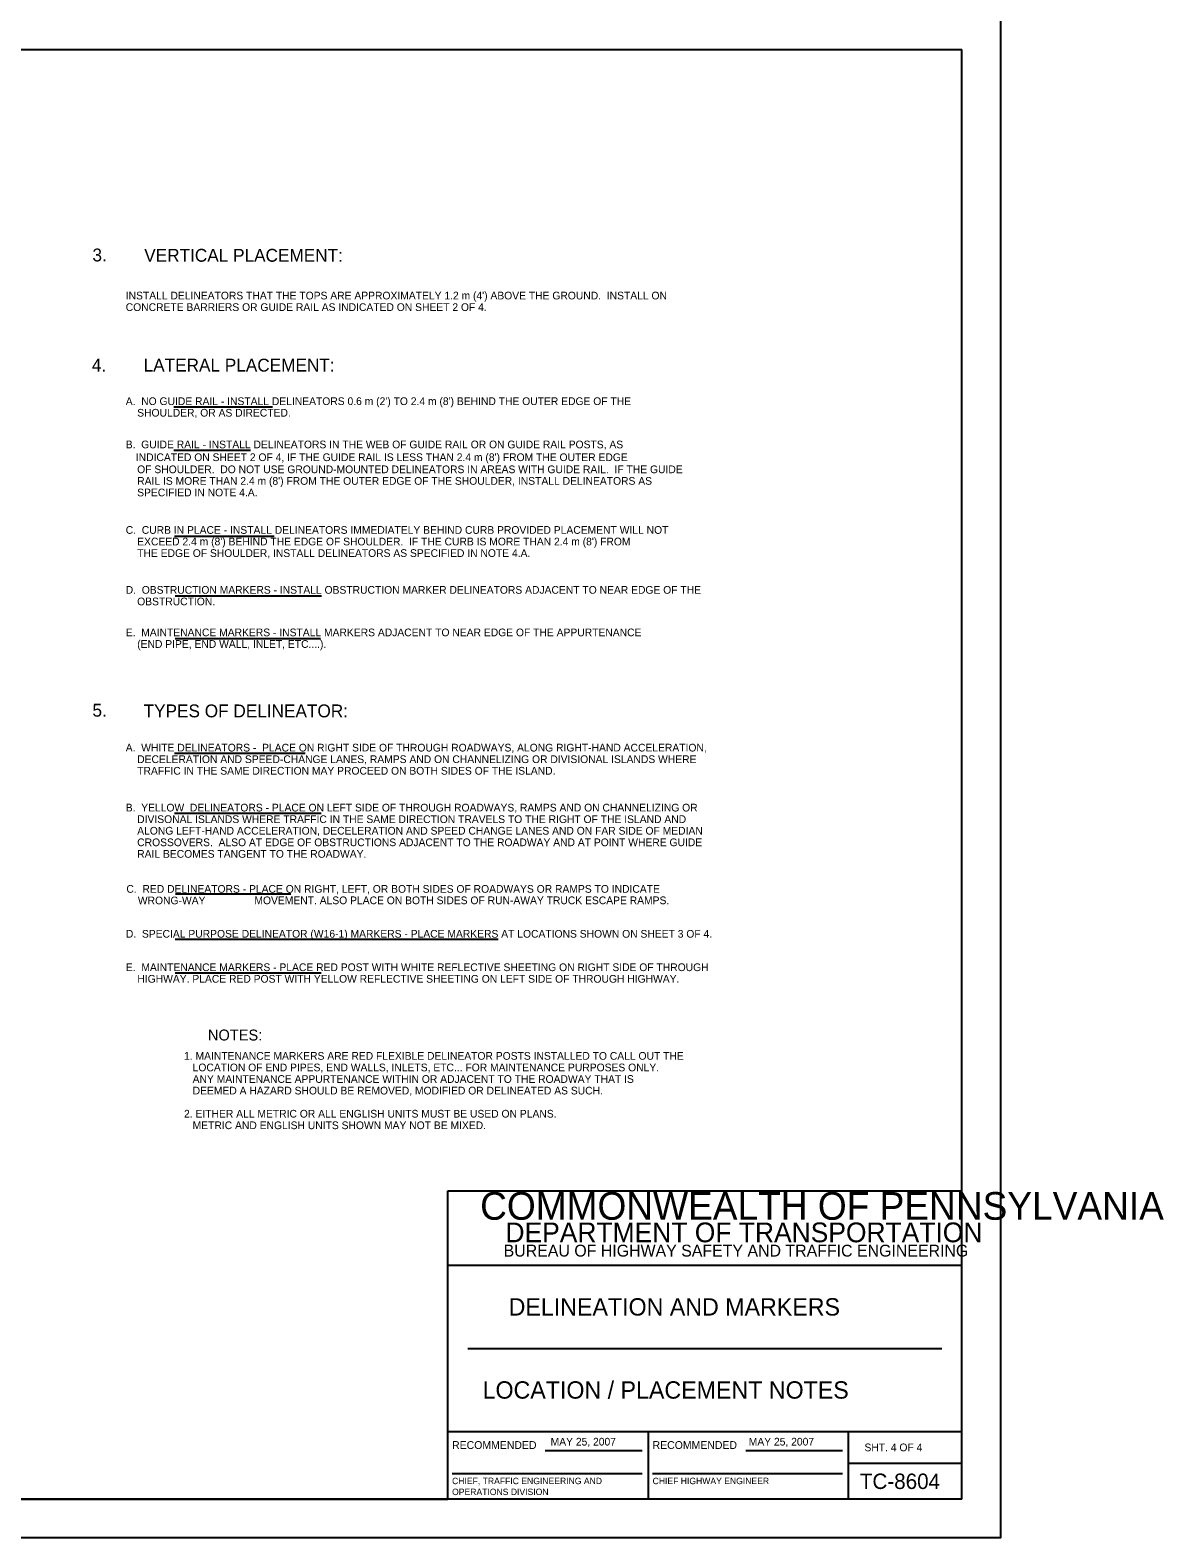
# Model space of a CAD drawing. Extents: x 640253 to 641999, y 298458 to 299646.
# Drawn here: x 641558 to 641999, y 298458 to 299044 of the extents above; entities that cross this region are included whole.
import ezdxf

# ---------------------------------------------------------------- set-up
doc = ezdxf.new("R2010")
doc.units = 0
for name, color, linetype in [('1', 7, 'Continuous'), ('2', 7, 'Continuous'), ('PLT-BNDY', 7, 'Continuous')]:
    doc.layers.add(name, color=color, linetype=linetype)

msp = doc.modelspace()

# ---------------------------------------------------------------- linework, layer by layer
at = {"layer": '1'}
for p, q in [((641134.31, 299036.63), (641920.31, 299036.63)), ((641920.31, 298472.63), (641920.31, 299036.63)), ((641720.31, 298472.63), (641720.31, 298592.63)), ((641720.31, 298592.63), (641920.31, 298592.63)), ((641920.31, 298563.63), (641720.31, 298563.63)), ((641728.06, 298531.31), (641912.56, 298531.31)), ((641720.31, 298499), (641920.31, 298499)), ((641798.31, 298499), (641798.31, 298472.63)), ((641876.19, 298472.63), (641876.19, 298499)), ((641758.24, 298491.57), (641795.87, 298491.57)), ((641836.24, 298491.57), (641873.87, 298491.57)), ((641721.99, 298482.68), (641795.87, 298482.68)), ((641799.99, 298482.68), (641873.87, 298482.68)), ((641876.19, 298486.63), (641920.31, 298486.63)), ((641920.31, 298472.63), (641134.31, 298472.63)), ((641134.31, 298472.63), (641720.31, 298472.63))]:
    msp.add_line(p, q, dxfattribs=at)
at = {"layer": '2'}
for p, q in [((641613.73, 298897.59), (641652.08, 298897.59)), ((641613.73, 298880.68), (641643.54, 298880.68)), ((641613.99, 298847.24), (641652.76, 298847.24)), ((641614.25, 298824.09), (641671.21, 298824.09)), ((641614.25, 298807.53), (641670.78, 298807.53)), ((641613.99, 298762.89), (641664.87, 298762.89)), ((641613.99, 298739.54), (641671.05, 298739.54)), ((641614.46, 298708.18), (641659.32, 298708.18)), ((641614.33, 298690.48), (641739.94, 298690.48)), ((641614.33, 298677.47), (641671.03, 298677.47))]:
    msp.add_line(p, q, dxfattribs=at)
at = {"layer": 'PLT-BNDY'}
msp.add_lwpolyline([(641094.31, 299051.63), (641935.31, 299051.63), (641935.31, 298457.63), (641094.31, 298457.63)], close=True, dxfattribs=at)

# ---------------------------------------------------------------- texts
at = {"layer": '1'}
for s, height, p in [('COMMONWEALTH OF PENNSYLVANIA', 10.7828, (641732.9, 298581.36)), ('DEPARTMENT OF TRANSPORTATION', 7.6837, (641742.76, 298572.61)), ('BUREAU OF HIGHWAY SAFETY AND TRAFFIC ENGINEERING', 4.6253, (641742.04, 298567.04)), ('DELINEATION AND MARKERS', 6.75, (641743.99, 298544.1)), ('LOCATION / PLACEMENT NOTES', 6.75, (641733.86, 298511.78)), ('RECOMMENDED', 3.048, (641721.99, 298492.2)), ('RECOMMENDED', 3.048, (641799.99, 298492.2)), ('SHT. 4 OF 4', 3, (641882.4, 298491.31)), ('TC-8604', 6, (641880.6, 298476.63)), ('OPERATIONS DIVISION', 2.5, (641721.99, 298474.26)), ('CHIEF, TRAFFIC ENGINEERING AND', 2.5, (641721.99, 298478.51)), ('CHIEF HIGHWAY ENGINEER', 2.5, (641799.99, 298478.51))]:
    msp.add_text(s, height=height, dxfattribs=at).set_placement(p)
at = {"layer": '2'}
for s, height, p in [('3.', 5, (641582.09, 298954.17)), ('VERTICAL PLACEMENT:', 5, (641602.24, 298954.04)), ("    INSTALL DELINEATORS THAT THE TOPS ARE APPROXIMATELY 1.2 m (4') ABOVE THE GROUND.  INSTALL ON ", 3, (641590.58, 298939.38)), ('    CONCRETE BARRIERS OR GUIDE RAIL AS INDICATED ON SHEET 2 OF 4.', 3, (641590.58, 298934.88)), ('4.', 5, (641581.84, 298911.32)), ('LATERAL PLACEMENT:', 5, (641601.99, 298911.32)), ("    A.  NO GUIDE RAIL - INSTALL DELINEATORS 0.6 m (2') TO 2.4 m (8') BEHIND THE OUTER EDGE OF THE ", 3, (641590.58, 298898.29)), ('        SHOULDER, OR AS DIRECTED.', 3, (641590.58, 298893.79)), ('    B.  GUIDE RAIL - INSTALL DELINEATORS IN THE WEB OF GUIDE RAIL OR ON GUIDE RAIL POSTS, AS', 3, (641590.58, 298881.46)), ("        INDICATED ON SHEET 2 OF 4, IF THE GUIDE RAIL IS LESS THAN 2.4 m (8') FROM THE OUTER EDGE", 3, (641590.05, 298876.49)), ('        OF SHOULDER.  DO NOT USE GROUND-MOUNTED DELINEATORS IN AREAS WITH GUIDE RAIL.  IF THE GUIDE', 3, (641590.58, 298871.78)), ("        RAIL IS MORE THAN 2.4 m (8') FROM THE OUTER EDGE OF THE SHOULDER, INSTALL DELINEATORS AS", 3, (641590.58, 298867.28)), ('        SPECIFIED IN NOTE 4.A. ', 3, (641590.58, 298862.78)), ('    C.  CURB IN PLACE - INSTALL DELINEATORS IMMEDIATELY BEHIND CURB PROVIDED PLACEMENT WILL NOT', 3, (641590.58, 298848.2)), ("        EXCEED 2.4 m (8') BEHIND THE EDGE OF SHOULDER.  IF THE CURB IS MORE THAN 2.4 m (8') FROM ", 3, (641590.58, 298843.7)), ('        THE EDGE OF SHOULDER, INSTALL DELINEATORS AS SPECIFIED IN NOTE 4.A.    ', 3, (641590.58, 298839.2)), ('    D.  OBSTRUCTION MARKERS - INSTALL OBSTRUCTION MARKER DELINEATORS ADJACENT TO NEAR EDGE OF THE', 3, (641590.58, 298824.89)), ('        OBSTRUCTION.', 3, (641590.58, 298820.39)), ('    E.  MAINTENANCE MARKERS - INSTALL MARKERS ADJACENT TO NEAR EDGE OF THE APPURTENANCE', 3, (641590.58, 298808.34)), ('        (END PIPE, END WALL, INLET, ETC....).', 3, (641590.58, 298803.84)), ('5.', 5, (641582.09, 298777.07)), ('TYPES OF DELINEATOR:', 5, (641601.99, 298776.81)), ('    A.  WHITE DELINEATORS -  PLACE ON RIGHT SIDE OF THROUGH ROADWAYS, ALONG RIGHT-HAND ACCELERATION,', 3, (641590.58, 298763.52)), ('        TRAFFIC IN THE SAME DIRECTION MAY PROCEED ON BOTH SIDES OF THE ISLAND.', 3, (641590.58, 298754.52)), ('        DECELERATION AND SPEED-CHANGE LANES, RAMPS AND ON CHANNELIZING OR DIVISIONAL ISLANDS WHERE', 3, (641590.58, 298759.02)), ('    B.  YELLOW  DELINEATORS - PLACE ON LEFT SIDE OF THROUGH ROADWAYS, RAMPS AND ON CHANNELIZING OR', 3, (641590.58, 298740.19)), ('        ALONG LEFT-HAND ACCELERATION, DECELERATION AND SPEED CHANGE LANES AND ON FAR SIDE OF MEDIAN', 3, (641590.58, 298731.19)), ('        DIVISONAL ISLANDS WHERE TRAFFIC IN THE SAME DIRECTION TRAVELS TO THE RIGHT OF THE ISLAND AND', 3, (641590.58, 298735.69)), ('        CROSSOVERS.  ALSO AT EDGE OF OBSTRUCTIONS ADJACENT TO THE ROADWAY AND AT POINT WHERE GUIDE', 3, (641590.58, 298726.69)), ('        RAIL BECOMES TANGENT TO THE ROADWAY.', 3, (641590.58, 298722.19)), ('    C.  RED DELINEATORS - PLACE ON RIGHT, LEFT, OR BOTH SIDES OF ROADWAYS OR RAMPS TO INDICATE', 3, (641590.84, 298708.57)), ('        WRONG-WAY ', 3, (641590.84, 298704.07)), ('MOVEMENT. ALSO PLACE ON BOTH SIDES OF RUN-AWAY TRUCK ESCAPE RAMPS.', 3, (641645.09, 298704.12)), ('    D.  SPECIAL PURPOSE DELINEATOR (W16-1) MARKERS - PLACE MARKERS AT LOCATIONS SHOWN ON SHEET 3 OF 4.', 3, (641590.64, 298691.1)), ('    E.  MAINTENANCE MARKERS - PLACE RED POST WITH WHITE REFLECTIVE SHEETING ON RIGHT SIDE OF THROUGH', 3, (641590.64, 298678.09)), ('        HIGHWAY. PLACE RED POST WITH YELLOW REFLECTIVE SHEETING ON LEFT SIDE OF THROUGH HIGHWAY.', 3, (641590.64, 298673.59)), ('NOTES:', 4.25, (641627, 298651.1)), ('1. MAINTENANCE MARKERS ARE RED FLEXIBLE DELINEATOR POSTS INSTALLED TO CALL OUT THE', 3, (641617.72, 298643.61)), ('   LOCATION OF END PIPES, END WALLS, INLETS, ETC... FOR MAINTENANCE PURPOSES ONLY.', 3, (641617.72, 298639.11)), ('   ANY MAINTENANCE APPURTENANCE WITHIN OR ADJACENT TO THE ROADWAY THAT IS', 3, (641617.72, 298634.61)), ('   DEEMED A HAZARD SHOULD BE REMOVED, MODIFIED OR DELINEATED AS SUCH.', 3, (641617.72, 298630.11)), ('2. EITHER ALL METRIC OR ALL ENGLISH UNITS MUST BE USED ON PLANS.  ', 3, (641617.72, 298621.11)), ('   METRIC AND ENGLISH UNITS SHOWN MAY NOT BE MIXED.', 3, (641617.72, 298616.61)), ('MAY 25, 2007', 3, (641760.32, 298493.53)), ('MAY 25, 2007', 3, (641837.39, 298493.53))]:
    msp.add_text(s, height=height, dxfattribs=at).set_placement(p)

doc.saveas('drawing.dxf')
